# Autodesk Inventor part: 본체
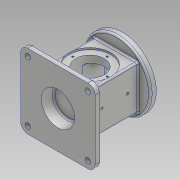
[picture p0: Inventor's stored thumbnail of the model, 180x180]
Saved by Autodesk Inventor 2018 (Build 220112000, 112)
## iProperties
Created: 2021-05
Part Number: 본체
Material: 알루미늄 6061
Document SubType Name: Modeling
Designer: home
Density: 2.7 g/cm^3
Appearance: 알루미늄 - 평지
Author: home
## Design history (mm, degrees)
sketch "스케치2"
  geometry: L1 (37, -37)-(-37, -37); L2 (-37, -37)-(-37, 37); L3 (-37, 37)-(37, 37); L4 (37, 37)-(37, -37); 1 further point
  constraints: 8 end point, 2 parallel, 1 horizontal, 1 perpendicular
  dimensions: "d4" = 74 distance between parallel lines of L2 L4; "d5" = 74 distance between parallel lines of L3 L1; "d6" = 37 distance from line of point (0, 0) L1; "d7" = 37 distance from line of point (0, 0) L4
extrude "돌출1" new body sketch "스케치2" distance "d8" = 88; taper "d9" = 0 deg
sketch "스케치3"
  geometry: L1 (74, 0)-(0, 0) reference; C1 r 24 at (37, 44); 2 further points
  constraints: 1 centre point, 1 midpoint, 1 vertical alignment
  dimensions: "d10" = 48 diameter of C1; "d11" = 44 distance from line of L1 C1.centre
extrude "돌출2" cut sketch "스케치3" distance "d12" = 88; taper "d13" = 0 deg
sketch "스케치4"
  geometry: C1 r 57.5 at (0, 0); 1 further point
  constraints: 1 centre point, 1 coincident
  dimensions: "d14" = 115 diameter of C1
extrude "돌출3" join sketch "스케치4" distance "d15" = 10; taper "d16" = 0 deg
sketch "스케치7"
  geometry: L1 (74, 0)-(0, 0) reference; L2 (74, 0)-(74, 88) reference; L3 (0, 88)-(74, 88) reference; L4 (0, 0)-(0, 88) reference; C1 r 24 at (37, 44) reference; C2 r 35 at (37, 44); 1 further point
  constraints: 1 centre point, 1 coincident
  dimensions: "d23" = 70 diameter of C2
extrude "돌출6" cut sketch "스케치7" distance "d24" = 3; taper "d25" = 0 deg
sketch "스케치8"
  geometry: L1 (37, -44)-(-37, -44) reference; C1 r 24 at (0, 0) reference; C2 r 35 at (0, 0) reference; 3 further points
  constraints: 1 midpoint, 1 vertical alignment
  dimensions: "d27" = 29 distance of point (0, 29) C1.centre
hole "구멍1" sketch "스케치8" at (0, 29) diameter "d28" = 3.242; stored, may be unused: countersink angle "d32" = 90 deg, drill point angle "d34" = 118 deg; dims "d29" = 8, "d30" = 4, "d31" = 2, "d33" = 10
sketch "스케치9"
  geometry: L1 (74, 0)-(0, 0) reference; 5 further points
  constraints: 2 midpoint, 2 vertical alignment
  dimensions: "d38" = 43 distance of point (37, 70) point (37, 27); "d39" = 27 distance of point (37, 0) point (37, 27)
hole "구멍2" sketch "스케치9" at (37, 70), (37, 27) diameter "d40" = 4.134; stored, may be unused: countersink angle "d44" = 90 deg, drill point angle "d46" = 118 deg; dims "d41" = 30, "d42" = 4, "d43" = 2, "d45" = 30
sketch "스케치10"
  geometry: L1 (-26, -26)-(26, -26); L2 (26, -26)-(26, 26); L3 (26, 26)-(-26, 26); L4 (-26, 26)-(-26, -26); 1 further point
  constraints: 8 end point, 2 parallel, 1 horizontal, 1 perpendicular
  dimensions: "d47" = 26 distance from line of point (0, 0) L1; "d48" = 52 distance between parallel lines of L3 L1; "d49" = 26 distance from line of point (0, 0) L4; "d50" = 52 distance between parallel lines of L2 L4
extrude "돌출7" cut sketch "스케치10" distance "d51" = 8; taper "d52" = 0 deg
sketch "스케치11"
  geometry: L1 (-22, -22)-(22, -22); L2 (22, -22)-(22, 22); L3 (22, 22)-(-22, 22); L4 (-22, 22)-(-22, -22); 1 further point
  constraints: 8 end point, 2 parallel, 1 horizontal, 1 perpendicular
  dimensions: "d53" = 22 distance from line of point (0, 0) L1; "d54" = 44 distance between parallel lines of L3 L1; "d55" = 22 distance from line of L4 point (0, 0); "d56" = 44 distance between parallel lines of L2 L4
extrude "돌출8" cut sketch "스케치11" distance "d57" = 74; taper "d58" = 0 deg
sketch "스케치13"
  geometry: L1 (33, -30)-(-33, -30); L2 (-33, -30)-(-33, 30); L3 (-33, 30)-(33, 30); L4 (33, 30)-(33, -30); 5 further points
  constraints: 8 end point, 4 coincident, 2 parallel, 1 horizontal, 1 perpendicular
  dimensions: "d59" = 66 distance of L1.start L1.end; "d60" = 60 distance of L1.end L2.end; "d61" = 30 distance from line of L3 point (0, 0); "d62" = 33 distance from line of point (0, 0) L4
hole "구멍3" sketch "스케치13" at (33, -30), (-33, -30), (-33, 30), (33, 30) diameter "d63" = 3.242; stored, may be unused: countersink angle "d67" = 90 deg, drill point angle "d69" = 118 deg; dims "d64" = 8, "d65" = 4, "d66" = 2, "d68" = 10
fillet "모깎기1" dims "d70" = 6
fillet "모깎기2" dims "d71" = 3
fillet "모깎기3" dims "d72" = 3
chamfer "모따기1" distance "d73" = 1; stored, may be unused: second distance "d74" = 2, angle "d75" = 45 deg
sketch "스케치14"
  geometry: L1 (-62.5, 62.5)-(62.5, 62.5); L2 (62.5, 62.5)-(62.5, -62.5); L3 (62.5, -62.5)-(-62.5, -62.5); L4 (-62.5, -62.5)-(-62.5, 62.5); 1 further point
  constraints: 8 end point, 2 parallel, 1 horizontal, 1 perpendicular
  dimensions: "d76" = 62.5 distance from line of L4 point (0, 0); "d77" = 125 distance between parallel lines of L2 L4; "d78" = 125 distance between parallel lines of L3 L1; "d79" = 62.5 distance from line of L3 point (0, 0)
extrude "돌출9" join sketch "스케치14" distance "d80" = 10; taper "d81" = 0 deg
fillet "모깎기4" dims "d82" = 12
sketch "스케치15"
  geometry: L1 (-62.5, -50.5)-(-62.5, 50.5) reference; L2 (-50.5, 62.5)-(50.5, 62.5) reference; L3 (62.5, 50.5)-(62.5, -50.5) reference; L4 (50.5, -62.5)-(-50.5, -62.5) reference; C1 r 4.5 at (-50.5, 50.5); C2 r 4.5 at (-50.5, -50.5); C3 r 4.5 at (50.5, -50.5); C4 r 4.5 at (50.5, 50.5); A1 r 12 centre (-50.5, -50.5) between (-62.5, -50.5) and (-50.5, -62.5) reference; A2 r 12 centre (-50.5, 50.5) between (-50.5, 62.5) and (-62.5, 50.5) reference; A3 r 12 centre (50.5, 50.5) between (62.5, 50.5) and (50.5, 62.5) reference; A4 r 12 centre (50.5, -50.5) between (50.5, -62.5) and (62.5, -50.5) reference; 1 further point
  constraints: 4 centre point, 4 coincident
  dimensions: "d83" = 9 diameter of C1; "d84" = 9 diameter of C2; "d85" = 9 diameter of C3; "d86" = 9 diameter of C4
extrude "돌출10" cut sketch "스케치15" distance "d87" = 10; taper "d88" = 0 deg
fillet "모깎기5" dims "d89" = 3
sketch "스케치16"
  geometry: 2 further points
  constraints: 1 vertical alignment, 1 other
  dimensions: "d90" = 55 distance of point (0, -55) point (0, 0)
feature "엠보싱1" sketch "스케치16" dims "d4" = 74, "d5" = 74, "d6" = 37, "d7" = 37, "d91" = 0.5, "d92" = 0
fillet "모깎기6" dims "d93" = 3
fillet "모깎기7" dims "d94" = 3
sketch "스케치17"
  geometry: C1 r 28 at (0, 0); 1 further point
  constraints: 1 centre point, 1 coincident
  dimensions: "d95" = 56 diameter of C1
extrude "돌출11" cut sketch "스케치17" distance "d96" = 18; taper "d97" = -10 deg
fillet "모깎기8" dims "d98" = 3
fillet "모깎기9" dims "d99" = 3
node "솔리드1"
pattern_circular "원형 패턴1" dims angle "d36" = 360 deg
mirror "미러1"
node "투영된 루프1"
node "투영된 루프2"
node "투영된 루프3"
